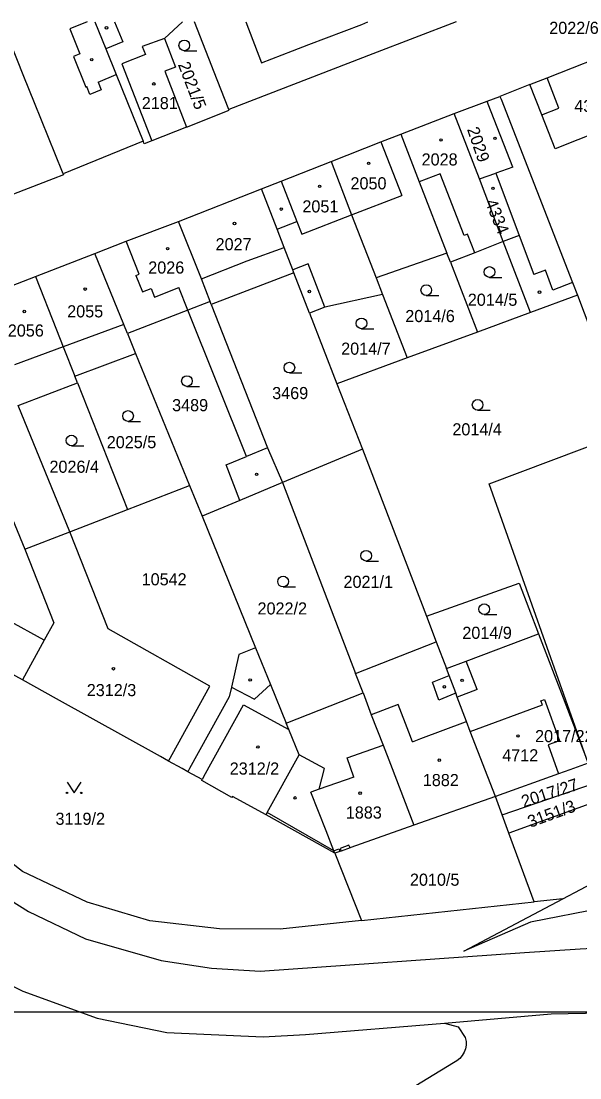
# Model space of a CAD drawing. Extents: x -564952 to -564307, y -1202373 to -1201847.
# Drawn here: x -564632.5 to -564554, y -1201998.3 to -1201849.9 of the extents above; entities that cross this region are included whole.
import ezdxf

# ---------------------------------------------------------------- set-up
doc = ezdxf.new("R2010")
doc.units = 0
for name, color, linetype in [('Hranice parcel', 7, 'Continuous'), ('Parcelní čísla', 7, 'Continuous'), ('Vnitřní kresba', 7, 'Continuous'), ('Vrstva 63', 7, 'Continuous'), ('Značky budov', 7, 'Continuous'), ('Značky kultur', 7, 'Continuous')]:
    doc.layers.add(name, color=color, linetype=linetype)

msp = doc.modelspace()

# ---------------------------------------------------------------- linework, layer by layer
at = {"layer": 'Hranice parcel'}
for p, q in [((-564619.09, -1201857.46), (-564615.32, -1201866.78)), ((-564560.98, -1201858.86), (-564565.18, -1201860.51)), ((-564565.18, -1201860.51), (-564565.03, -1201860.92)), ((-564579.11, -1201865.81), (-564571.61, -1201862.92)), ((-564568.08, -1201872.1), (-564571.61, -1201862.92)), ((-564615.32, -1201866.78), (-564626.56, -1201871.38)), ((-564588.91, -1201869.65), (-564586.03, -1201877.14)), ((-564564.71, -1201880.9), (-564568.08, -1201872.1)), ((-564610.36, -1201878.05), (-564598.69, -1201873.5)), ((-564586.03, -1201877.14), (-564582.59, -1201885.96)), ((-564607.13, -1201886.12), (-564610.36, -1201878.05)), ((-564560.9, -1201890.85), (-564564.71, -1201880.9)), ((-564630.43, -1201885.8), (-564622.09, -1201882.54)), ((-564572.64, -1201882.5), (-564582.59, -1201885.96)), ((-564572.14, -1201883.78), (-564572.64, -1201882.5)), ((-564572.14, -1201883.78), (-564568.34, -1201893.59)), ((-564594.12, -1201885.29), (-564605.73, -1201889.7)), ((-564591.93, -1201890.94), (-564594.12, -1201885.29)), ((-564630.43, -1201885.8), (-564627.48, -1201893.3)), ((-564582.59, -1201885.96), (-564581.67, -1201888.32)), ((-564581.67, -1201888.32), (-564578.2, -1201897.22)), ((-564554.29, -1201888.42), (-564560.9, -1201890.85)), ((-564554.29, -1201888.42), (-564552.42, -1201893.39)), ((-564591.93, -1201890.94), (-564588.08, -1201900.86)), ((-564560.9, -1201890.85), (-564568.34, -1201893.59)), ((-564617.5, -1201893.79), (-564616.36, -1201896.58)), ((-564568.34, -1201893.59), (-564578.2, -1201897.22)), ((-564624.91, -1201899.78), (-564616.36, -1201896.58)), ((-564616.36, -1201896.58), (-564608.79, -1201915.11)), ((-564578.2, -1201897.22), (-564588.08, -1201900.86)), ((-564624.54, -1201900.73), (-564624.91, -1201899.78)), ((-564632.88, -1201903.92), (-564624.54, -1201900.73)), ((-564624.54, -1201900.73), (-564617.51, -1201918.49)), ((-564588.08, -1201900.86), (-564584.48, -1201910.01)), ((-564625.61, -1201921.62), (-564632.88, -1201903.92)), ((-564584.48, -1201910.01), (-564595.73, -1201914.71)), ((-564584.48, -1201910.01), (-564575.5, -1201933.47)), ((-564595.73, -1201914.71), (-564601.71, -1201917.21)), ((-564595.73, -1201914.71), (-564585.46, -1201941.52)), ((-564617.51, -1201918.49), (-564608.79, -1201915.11)), ((-564608.79, -1201915.11), (-564607.03, -1201919.43)), ((-564634.72, -1201917.22), (-564631.93, -1201924.07)), ((-564601.71, -1201917.21), (-564607.03, -1201919.43)), ((-564625.61, -1201921.62), (-564617.51, -1201918.49)), ((-564607.03, -1201919.43), (-564599.52, -1201937.9)), ((-564631.93, -1201924.07), (-564625.61, -1201921.62)), ((-564631.93, -1201924.07), (-564627.85, -1201934.4)), ((-564575.5, -1201933.47), (-564574.13, -1201937.05)), ((-564585.46, -1201941.52), (-564574.13, -1201937.05)), ((-564574.13, -1201937.05), (-564572.71, -1201940.81)), ((-564599.52, -1201937.9), (-564601.88, -1201938.86)), ((-564584.42, -1201944.24), (-564585.46, -1201941.52)), ((-564595.21, -1201948.49), (-564584.42, -1201944.24)), ((-564594.85, -1201949.38), (-564595.21, -1201948.49)), ((-564564.86, -1201961.36), (-564551.91, -1201956.9)), ((-564565.82, -1201958.76), (-564577.26, -1201962.81)), ((-564564.86, -1201961.36), (-564565.82, -1201958.76)), ((-564551.03, -1201959.23), (-564563.92, -1201963.93)), ((-564588.36, -1201966.75), (-564598.04, -1201961.33)), ((-564563.92, -1201963.93), (-564564.86, -1201961.36)), ((-564560.38, -1201973.55), (-564563.92, -1201963.93)), ((-564588.36, -1201966.75), (-564584.64, -1201976.16)), ((-564556.34, -1201973.12), (-564551.4, -1201970.51)), ((-564584.64, -1201976.16), (-564560.38, -1201973.55)), ((-564570.25, -1201980.49), (-564556.34, -1201973.12)), ((-564556.34, -1201973.12), (-564560.38, -1201973.55)), ((-564584.64, -1201976.16), (-564596.05, -1201977.38))]:
    msp.add_line(p, q, dxfattribs=at)
for points in [[(-564626.56, -1201871.38), (-564626.65, -1201871.15), (-564630.57, -1201861.4), (-564632.05, -1201857.71), (-564635.12, -1201850.07)], [(-564622.09, -1201850.07), (-564620.57, -1201853.84), (-564619.09, -1201857.46)], [(-564609.78, -1201850.07), (-564612.33, -1201852.38), (-564610.77, -1201856.4), (-564612.26, -1201856.98), (-564609.22, -1201864.81)], [(-564603.26, -1201862.34), (-564604.89, -1201858.19), (-564608.1, -1201850.07)], [(-564571.35, -1201850.07), (-564583.04, -1201854.52), (-564603.26, -1201862.34)], [(-564560.98, -1201858.86), (-564558.55, -1201857.91), (-564548.1, -1201853.81)], [(-564544.7, -1201862.84), (-564557.45, -1201867.85), (-564559.32, -1201863.1), (-564560.98, -1201858.86)], [(-564571.61, -1201862.92), (-564566.97, -1201861.19), (-564565.18, -1201860.51)], [(-564565.03, -1201860.92), (-564554.98, -1201886.65), (-564554.29, -1201888.42)], [(-564609.22, -1201864.81), (-564603.22, -1201862.44), (-564603.26, -1201862.34)], [(-564609.22, -1201864.81), (-564614.1, -1201866.74), (-564615.17, -1201867.16), (-564615.32, -1201866.78)], [(-564588.91, -1201869.65), (-564581.91, -1201866.91), (-564579.11, -1201865.81)], [(-564579.11, -1201865.81), (-564576.51, -1201872.52), (-564572.64, -1201882.5)], [(-564598.69, -1201873.5), (-564595.9, -1201872.4), (-564588.91, -1201869.65)], [(-564686.16, -1201871.23), (-564677.08, -1201895.29), (-564660.17, -1201939.88), (-564659.23, -1201942.17), (-564652.34, -1201954.8), (-564647.57, -1201960.74), (-564641.3, -1201967.43), (-564636.51, -1201971.74), (-564631.4, -1201974.9), (-564623.41, -1201978.76)], [(-564626.56, -1201871.38), (-564626.5, -1201871.52), (-564627.97, -1201872.09), (-564634.97, -1201874.82)], [(-564568.08, -1201872.1), (-564565.78, -1201871.3), (-564562.49, -1201880.04), (-564564.71, -1201880.9)], [(-564594.12, -1201885.29), (-564594.29, -1201884.86), (-564595.51, -1201881.7), (-564596.49, -1201879.16), (-564598.69, -1201873.5)], [(-564622.09, -1201882.54), (-564617.68, -1201880.84), (-564610.36, -1201878.05)], [(-564564.71, -1201880.9), (-564568.73, -1201882.46), (-564572.14, -1201883.78)], [(-564617.5, -1201893.79), (-564618.01, -1201892.54), (-564622.09, -1201882.54)], [(-564638.96, -1201889.11), (-564637.47, -1201888.5), (-564630.43, -1201885.8)], [(-564605.73, -1201889.7), (-564605.89, -1201889.28), (-564607.13, -1201886.12)], [(-564581.67, -1201888.32), (-564589.79, -1201890.11), (-564591.93, -1201890.94)], [(-564605.73, -1201889.7), (-564597.83, -1201909.85), (-564595.73, -1201914.71)], [(-564601.71, -1201917.21), (-564603.64, -1201912.23), (-564600.77, -1201911.06), (-564609.03, -1201890.5), (-564617.5, -1201893.79)], [(-564627.48, -1201893.3), (-564626.54, -1201895.68), (-564624.91, -1201899.78)], [(-564552.78, -1201954.12), (-564566.71, -1201914.88), (-564553.62, -1201910), (-564547.1, -1201907.51)], [(-564611.74, -1201953.8), (-564605.93, -1201943.27), (-564620.21, -1201935.26), (-564625.61, -1201921.62)], [(-564575.5, -1201933.47), (-564562.5, -1201928.84), (-564559.77, -1201935.95)], [(-564632.28, -1201942.4), (-564640.53, -1201937.84), (-564641.72, -1201937.18), (-564641.79, -1201937.31), (-564644.55, -1201935.78), (-564644.48, -1201935.65), (-564650.19, -1201932.49)], [(-564627.85, -1201934.4), (-564629.21, -1201936.85), (-564632.28, -1201942.4)], [(-564572.71, -1201940.81), (-564569.93, -1201939.76), (-564559.77, -1201935.95)], [(-564559.77, -1201935.95), (-564556.55, -1201944.31), (-564552.78, -1201954.12)], [(-564599.52, -1201937.9), (-564597.42, -1201943.05), (-564595.21, -1201948.49)], [(-564601.88, -1201938.86), (-564602.91, -1201943.41), (-564603.23, -1201944.81), (-564608.78, -1201954.86), (-564609.02, -1201955.3)], [(-564565.82, -1201958.76), (-564569.35, -1201949.64), (-564569.88, -1201948.24), (-564571.18, -1201944.82), (-564571.38, -1201944.24), (-564572.31, -1201941.81), (-564572.71, -1201940.81)], [(-564611.74, -1201953.8), (-564612.87, -1201953.17), (-564627.49, -1201945.06), (-564632.28, -1201942.4)], [(-564584.42, -1201944.24), (-564583.26, -1201947.33), (-564581.6, -1201951.56), (-564580.56, -1201954.26), (-564577.26, -1201962.81)], [(-564596.05, -1201977.38), (-564604.58, -1201977.37), (-564614.37, -1201976.21), (-564623.15, -1201973.61), (-564632.26, -1201969.32), (-564640.22, -1201963.11), (-564646.58, -1201956.32), (-564653.95, -1201945.36)], [(-564598.04, -1201961.33), (-564597.87, -1201961.02), (-564593.4, -1201952.95), (-564594.85, -1201949.38)], [(-564609.02, -1201955.3), (-564609.82, -1201954.85), (-564611.74, -1201953.8)], [(-564552.78, -1201954.12), (-564555.39, -1201955.05), (-564556.96, -1201955.61), (-564565.82, -1201958.76)], [(-564598.04, -1201961.33), (-564602.77, -1201958.77), (-564602.84, -1201958.9), (-564607.08, -1201956.55), (-564607.01, -1201956.41), (-564609.02, -1201955.3)], [(-564577.26, -1201962.81), (-564586.11, -1201965.95), (-564586.24, -1201966), (-564587.5, -1201966.44), (-564587.66, -1201966.5), (-564588.36, -1201966.75)], [(-564505.77, -1201989.55), (-564513.32, -1201982.96), (-564521.17, -1201979.06), (-564531.54, -1201975.72), (-564541.26, -1201974.14), (-564550.84, -1201974.47), (-564560.9, -1201976.42), (-564570.25, -1201980.49)], [(-564623.41, -1201978.76), (-564612.8, -1201981.8), (-564605.69, -1201982.88)], [(-564605.69, -1201982.88), (-564598.88, -1201983.3), (-564561.75, -1201980.66), (-564553.92, -1201980.18), (-564549.62, -1201979.94), (-564544.81, -1201979.95), (-564538.75, -1201980.64), (-564532.96, -1201982.16), (-564526.67, -1201985.07), (-564523.04, -1201987.55), (-564519.22, -1201990.84), (-564516.18, -1201994.23), (-564513.04, -1201998.5), (-564509.57, -1202004.53)], [(-564640.45, -1201981.26), (-564637.68, -1201983.33), (-564632.21, -1201986.09), (-564621.75, -1201989.88), (-564611.99, -1201991.88), (-564598.44, -1201992.53), (-564592.52, -1201992.17), (-564572.99, -1201990.58)], [(-564572.99, -1201990.58), (-564557.98, -1201989.28), (-564550.78, -1201989.16), (-564545.37, -1201989.69), (-564539.44, -1201991.01), (-564534.17, -1201993.43), (-564528.95, -1201996.43), (-564523.84, -1202000.46), (-564519.2, -1202005.26)], [(-564572.99, -1201990.58), (-564571.06, -1201991.11), (-564570.05, -1201992.61)], [(-564570.05, -1201992.61), (-564569.94, -1201993.14), (-564569.94, -1201993.68), (-564570.03, -1201994.21), (-564570.2, -1201994.68), (-564570.47, -1201995.14), (-564570.83, -1201995.55), (-564571.25, -1201995.89), (-564571.73, -1201996.14)], [(-564571.73, -1201996.14), (-564596.1, -1202011.05), (-564599.43, -1202013.53), (-564603.54, -1202017.13)]]:
    msp.add_lwpolyline(points, dxfattribs=at)
at = {"layer": 'Vnitřní kresba'}
for p, q in [((-564623.18, -1201850.07), (-564625.6, -1201851.05)), ((-564625.6, -1201851.05), (-564624.19, -1201854.54)), ((-564619.33, -1201850.07), (-564618.16, -1201852.86)), ((-564600.9, -1201850.07), (-564598.69, -1201855.81)), ((-564592.03, -1201853.25), (-564584.61, -1201850.4)), ((-564584.61, -1201850.4), (-564583.75, -1201850.07)), ((-564612.33, -1201852.38), (-564615.43, -1201853.51)), ((-564618.16, -1201852.86), (-564620.57, -1201853.84)), ((-564615.43, -1201853.51), (-564614.98, -1201854.65)), ((-564598.69, -1201855.81), (-564594.33, -1201854.13)), ((-564594.33, -1201854.13), (-564592.03, -1201853.25)), ((-564624.19, -1201854.54), (-564625.11, -1201854.91)), ((-564625.11, -1201854.91), (-564623.38, -1201859.2)), ((-564614.98, -1201854.65), (-564618.31, -1201855.95)), ((-564618.31, -1201855.95), (-564614.1, -1201866.74)), ((-564621.64, -1201858.5), (-564619.09, -1201857.46)), ((-564621.64, -1201858.5), (-564621.2, -1201859.58)), ((-564556.89, -1201862.15), (-564558.55, -1201857.91)), ((-564623.38, -1201859.2), (-564623.24, -1201859.14)), ((-564622.8, -1201860.23), (-564623.24, -1201859.14)), ((-564621.2, -1201859.58), (-564622.8, -1201860.23)), ((-564566.82, -1201861.59), (-564566.97, -1201861.19)), ((-564563.39, -1201870.46), (-564566.82, -1201861.59)), ((-564559.32, -1201863.1), (-564556.89, -1201862.15)), ((-564581.91, -1201866.91), (-564578.99, -1201874.4)), ((-564563.39, -1201870.46), (-564565.78, -1201871.3)), ((-564573.56, -1201871.38), (-564576.51, -1201872.52)), ((-564570.21, -1201880.02), (-564573.56, -1201871.38)), ((-564595.9, -1201872.4), (-564593.71, -1201878.09)), ((-564586.03, -1201877.14), (-564578.99, -1201874.4)), ((-564593.03, -1201879.87), (-564586.03, -1201877.14)), ((-564596.49, -1201879.16), (-564593.71, -1201878.09)), ((-564593.71, -1201878.09), (-564593.03, -1201879.87)), ((-564615.89, -1201885.45), (-564617.68, -1201880.84)), ((-564569.75, -1201879.84), (-564570.21, -1201880.02)), ((-564568.73, -1201882.46), (-564569.75, -1201879.84)), ((-564562.49, -1201880.04), (-564560.44, -1201885.5)), ((-564600.68, -1201883.6), (-564595.51, -1201881.7)), ((-564607.13, -1201886.12), (-564600.68, -1201883.6)), ((-564592.14, -1201884.03), (-564594.29, -1201884.86)), ((-564589.79, -1201890.11), (-564592.14, -1201884.03)), ((-564558.79, -1201884.88), (-564560.44, -1201885.5)), ((-564557.74, -1201887.69), (-564558.79, -1201884.88)), ((-564616.35, -1201885.64), (-564615.89, -1201885.45)), ((-564616.35, -1201885.64), (-564615.41, -1201887.93)), ((-564554.98, -1201886.65), (-564557.74, -1201887.69)), ((-564615.41, -1201887.93), (-564614.16, -1201887.47)), ((-564614.16, -1201887.47), (-564613.7, -1201888.69)), ((-564613.7, -1201888.69), (-564610.28, -1201887.35)), ((-564609.03, -1201890.5), (-564610.28, -1201887.35)), ((-564605.89, -1201889.28), (-564609.03, -1201890.5)), ((-564618.01, -1201892.54), (-564626.54, -1201895.68)), ((-564626.54, -1201895.68), (-564633.4, -1201898.2)), ((-564597.83, -1201909.85), (-564600.77, -1201911.06)), ((-564629.21, -1201936.85), (-564634.32, -1201934.04)), ((-564568.38, -1201943.75), (-564569.93, -1201939.76)), ((-564599.68, -1201945.1), (-564597.42, -1201943.05)), ((-564574.65, -1201942.71), (-564572.31, -1201941.81)), ((-564573.79, -1201945.25), (-564574.65, -1201942.71)), ((-564602.91, -1201943.41), (-564599.68, -1201945.1)), ((-564571.52, -1201944.3), (-564573.79, -1201945.25)), ((-564571.38, -1201944.24), (-564571.52, -1201944.3)), ((-564568.38, -1201943.75), (-564571.18, -1201944.82)), ((-564606.76, -1201955.98), (-564601.19, -1201945.92)), ((-564601.19, -1201945.92), (-564594.85, -1201949.38)), ((-564579.48, -1201945.88), (-564583.26, -1201947.33)), ((-564578, -1201949.74), (-564579.48, -1201945.88)), ((-564569.35, -1201949.64), (-564559.23, -1201945.91)), ((-564559.43, -1201945.37), (-564558.91, -1201945.18)), ((-564559.23, -1201945.91), (-564559.43, -1201945.37)), ((-564558.91, -1201945.18), (-564556.84, -1201950.98)), ((-564576.29, -1201950.65), (-564570.02, -1201948.29)), ((-564570.02, -1201948.29), (-564569.88, -1201948.24)), ((-564577.48, -1201951.1), (-564578, -1201949.74)), ((-564586.66, -1201953.34), (-564581.6, -1201951.56)), ((-564577.48, -1201951.1), (-564576.29, -1201950.65)), ((-564556.84, -1201950.98), (-564558.41, -1201951.54)), ((-564558.41, -1201951.54), (-564556.96, -1201955.61)), ((-564589.85, -1201954.85), (-564593.4, -1201952.95)), ((-564585.72, -1201956.05), (-564586.66, -1201953.34)), ((-564590.56, -1201957.73), (-564589.85, -1201954.85)), ((-564606.76, -1201955.98), (-564607.01, -1201956.41)), ((-564585.72, -1201956.05), (-564590.56, -1201957.73)), ((-564590.56, -1201957.73), (-564591.76, -1201958.15)), ((-564589.61, -1201963.6), (-564591.76, -1201958.15)), ((-564588.51, -1201966.38), (-564597.87, -1201961.02)), ((-564588.51, -1201966.38), (-564589.61, -1201963.6)), ((-564588.51, -1201966.38), (-564587.8, -1201966.12)), ((-564588.36, -1201966.75), (-564588.51, -1201966.38)), ((-564587.8, -1201966.12), (-564587.66, -1201966.5)), ((-564586.39, -1201965.59), (-564587.64, -1201966.06)), ((-564587.64, -1201966.06), (-564587.5, -1201966.44)), ((-564586.24, -1201966), (-564586.39, -1201965.59))]:
    msp.add_line(p, q, dxfattribs=at)
at = {"layer": 'Vrstva 63'}
msp.add_lwpolyline([(-564540.34, -1202137.49), (-564645.34, -1202137.49), (-564645.34, -1201988.99), (-564540.34, -1201988.99)], close=True, dxfattribs=at)
at = {"layer": 'Značky budov'}
for centre in [(-564620.45, -1201850.89), (-564622.53, -1201855.36), (-564613.81, -1201858.76), (-564573.46, -1201866.63), (-564565.89, -1201866.39), (-564583.63, -1201869.91), (-564590.52, -1201873.13), (-564566.17, -1201873.42), (-564595.9, -1201876.33), (-564602.48, -1201878.35), (-564611.87, -1201881.89), (-564623.45, -1201887.56), (-564591.96, -1201887.89), (-564559.63, -1201887.99), (-564632.01, -1201890.71), (-564599.37, -1201913.56), (-564619.48, -1201940.85), (-564600.28, -1201942.42), (-564570.5, -1201942.46), (-564572.99, -1201943.39), (-564562.65, -1201950.28), (-564599.19, -1201951.82), (-564573.7, -1201953.68), (-564593.97, -1201958.97), (-564584.83, -1201958.31)]:
    msp.add_circle(centre, 0.175, dxfattribs=at)
at = {"layer": 'Značky kultur'}
for p, q in [((-564609.53, -1201854.1), (-564607.78, -1201854.1)), ((-564566.65, -1201885.91), (-564564.9, -1201885.91)), ((-564575.53, -1201888.45), (-564573.78, -1201888.45)), ((-564584.64, -1201893.12), (-564582.89, -1201893.12)), ((-564594.77, -1201899.33), (-564593.02, -1201899.33)), ((-564609.15, -1201901.21), (-564607.4, -1201901.21)), ((-564568.32, -1201904.55), (-564566.57, -1201904.55)), ((-564617.43, -1201906.12), (-564615.68, -1201906.12)), ((-564625.38, -1201909.56), (-564623.63, -1201909.56)), ((-564583.98, -1201925.73), (-564582.23, -1201925.73)), ((-564595.65, -1201929.36), (-564593.9, -1201929.36)), ((-564567.39, -1201933.24), (-564565.64, -1201933.24))]:
    msp.add_line(p, q, dxfattribs=at)
msp.add_lwpolyline([(-564626, -1201956.77), (-564625, -1201958.27), (-564624, -1201956.77)], dxfattribs=at)
for centre, radius in [((-564609.53, -1201853.35), 0.75), ((-564566.65, -1201885.16), 0.75), ((-564575.53, -1201887.7), 0.75), ((-564584.64, -1201892.37), 0.75), ((-564594.77, -1201898.58), 0.75), ((-564609.15, -1201900.46), 0.75), ((-564568.32, -1201903.8), 0.75), ((-564617.43, -1201905.37), 0.75), ((-564625.38, -1201908.81), 0.75), ((-564583.98, -1201924.98), 0.75), ((-564595.65, -1201928.61), 0.75), ((-564567.39, -1201932.49), 0.75), ((-564626, -1201958.27), 0.1), ((-564624, -1201958.27), 0.1)]:
    msp.add_circle(centre, radius, dxfattribs=at)

# ---------------------------------------------------------------- texts
at = {"layer": 'Parcelní čísla'}
for s, p in [('2022/6', (-564558.26, -1201851.74)), ('2181', (-564615.5, -1201862.3)), ('4333', (-564554.74, -1201862.71)), ('2028', (-564576.19, -1201870.21)), ('2050', (-564586.18, -1201873.56)), ('2051', (-564592.94, -1201876.8)), ('2027', (-564605.13, -1201882.11)), ('2026', (-564614.59, -1201885.38)), ('2014/5', (-564569.7, -1201889.9)), ('2055', (-564625.98, -1201891.53)), ('2014/6', (-564578.48, -1201892.19)), ('2056', (-564634.32, -1201894.22)), ('2014/7', (-564587.49, -1201896.77)), ('3469', (-564597.18, -1201903)), ('3489', (-564611.24, -1201904.7)), ('2014/4', (-564571.87, -1201908.09)), ('2025/5', (-564620.42, -1201909.89)), ('2026/4', (-564628.47, -1201913.34)), ('10542', (-564615.52, -1201929.14)), ('2021/1', (-564587.16, -1201929.49)), ('2022/2', (-564599.24, -1201933.23)), ('2014/9', (-564570.47, -1201936.65)), ('2312/3', (-564623.23, -1201944.69)), ('2017/221', (-564560.25, -1201951.15)), ('4712', (-564564.86, -1201953.84)), ('2312/2', (-564603.15, -1201955.7)), ('1882', (-564576.02, -1201957.32)), ('3119/2', (-564627.62, -1201962.75)), ('1883', (-564586.84, -1201961.87)), ('2010/5', (-564577.83, -1201971.3))]:
    msp.add_text(s, height=1.7, dxfattribs=at).set_placement(p)
for s, rotation, p in [('2021/5', 291, (-564610.45, -1201856.03)), ('2029', 289, (-564569.83, -1201865.13)), ('4334', 292, (-564567.3, -1201875.34)), ('2017/27', 18, (-564561.85, -1201960.34)), ('3151/3', 20, (-564560.93, -1201963.18))]:
    msp.add_text(s, height=1.7, rotation=rotation, dxfattribs=at).set_placement(p)

doc.saveas('drawing.dxf')
